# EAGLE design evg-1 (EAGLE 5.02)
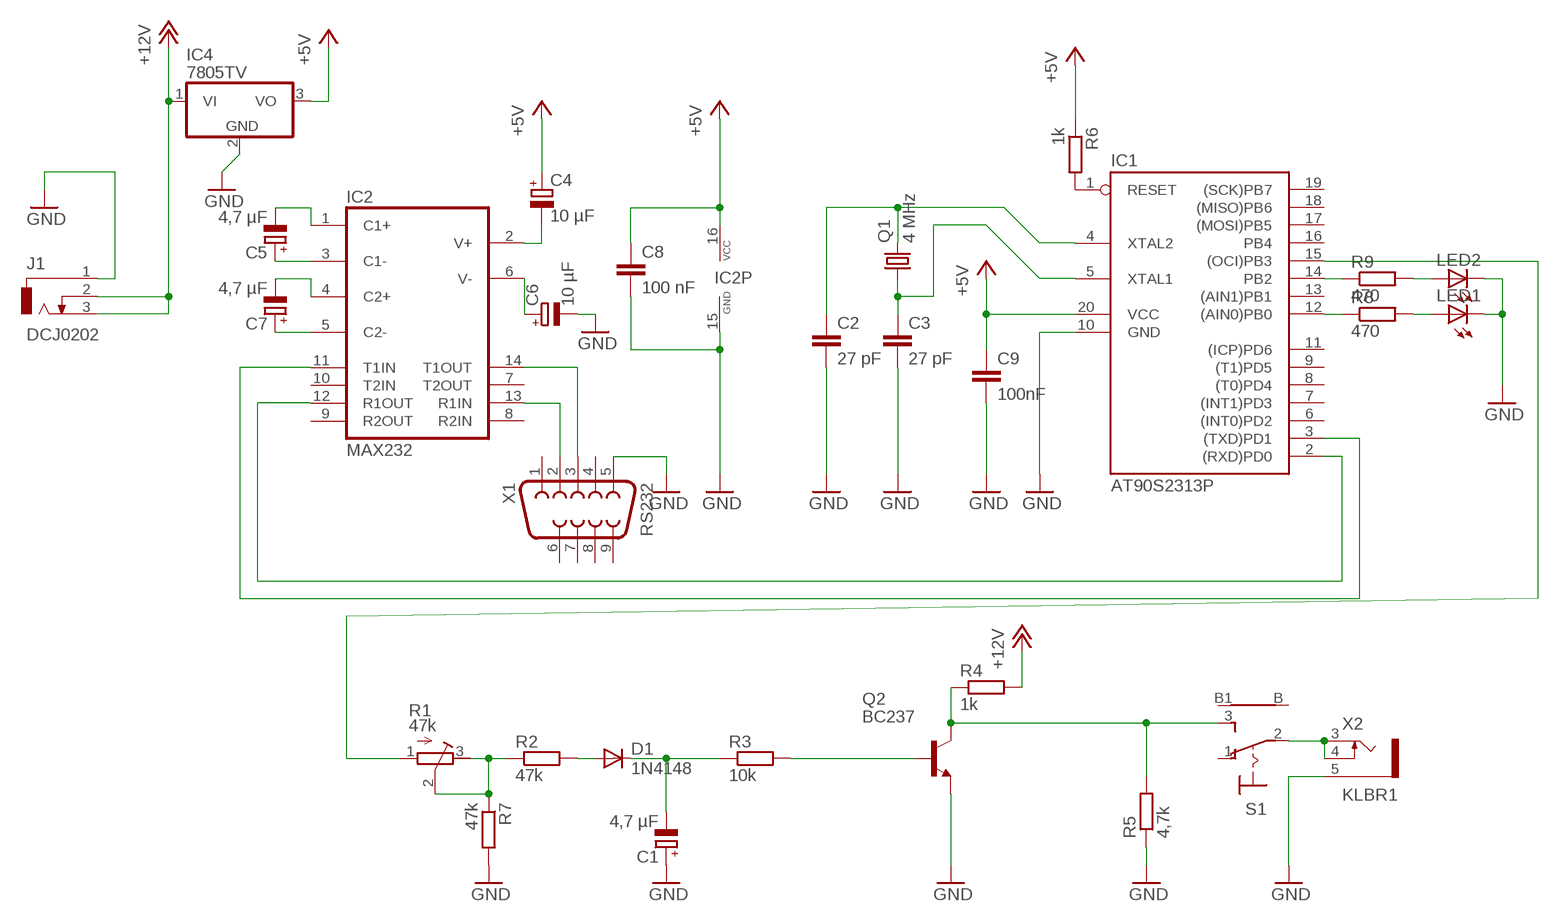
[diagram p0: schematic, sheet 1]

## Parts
C1  4,7 µF  CPOL-EUE2.5-6  [E2,5-6]
C2  27 pF  C-EU075-032X103  [C075-032X103]
C3  27 pF  C-EU075-032X103  [C075-032X103]
C4  10 µF  CPOL-EUE2.5-6  [E2,5-6]
C5  4,7 µF  CPOL-EUE2.5-6  [E2,5-6]
C6  10 µF  CPOL-EUE2.5-6  [E2,5-6]
C7  4,7 µF  CPOL-EUE2.5-6  [E2,5-6]
C8  100 nF  C-EU075-032X103  [C075-032X103]
C9  100nF  C-EU075-032X103  [C075-032X103]
D1  1N4148  [DO35-10]
IC1  AT90S2313P  [DIL20]
IC2  MAX232  [DIL16]
IC4  7805TV  [TO220V]
J1  DCJ0202  [DCJ0202]
LED1  LED3MM  [LED3MM]
LED2  LED3MM  [LED3MM]
Q1  4 MHz  CRYSTALHC18U-V  [HC18U-V]
Q2  BC237  [TO92]
R1  47k  R-TRIMM74W  [RTRIM74W]
R2  47k  R-EU_0207/15  [0207/15]
R3  10k  R-EU_0204/7  [0204/7]
R4  1k  R-EU_0207/15  [0207/15]
R5  4,7k  R-EU_0204/7  [0204/7]
R6  1k  R-EU_0204/7  [0204/7]
R7  47k  R-EU_0204/7  [0204/7]
R8  470  R-EU_0204/2V  [0204V]
R9  470  R-EU_0204/2V  [0204V]
S1  9070-1W  [9070-1W]
X1  RS232  F09H  [F09H]
X2  KLBR1  [KLBR1]

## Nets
+5V: C4.+ C8.1 C9.1 IC1.20(VCC) IC2.16(VCC) IC4.3(VO) R6.1
+12V: IC4.1(VI) J1.2 J1.3 R4.2
C6: C6.+ IC2.6(V-)
GND: C1.+ C2.2 C3.2 C6.- C8.2 C9.2 IC1.10(GND) IC2.15(GND) IC4.2(GND) J1.1 LED1.K(C) LED2.K(C) Q2.1(E) R5.1 R7.2 X1.5 X2.5
N$1: IC1.2((RXD)PD0) IC2.12(R1OUT)
N$2: IC1.1(RESET) R6.2
N$3: IC1.3((TXD)PD1) IC2.11(T1IN)
N$4: C7.+ IC2.5(C2-)
N$5: C5.+ IC2.3(C1-)
N$6: C2.1 IC1.4(XTAL2) Q1.2
N$7: C7.- IC2.4(C2+)
N$8: C5.- IC2.1(C1+)
N$9: C4.- IC2.2(V+)
N$10: S1.2(P) X2.3 X2.4
N$11: C3.1 IC1.5(XTAL1) Q1.1
N$13: IC2.13(R1IN) X1.2
N$14: IC2.14(T1OUT) X1.3
N$15: Q2.3(C) R4.1 R5.2 S1.3(S)
N$16: D1.A R2.2
N$17: R1.2(S) R1.3(A) R2.1 R7.1
N$18: C1.- D1.C R3.1
N$19: Q2.2(B) R3.2
N$20: IC1.14(PB2) R9.1
N$21: IC1.12((AIN0)PB0) R8.1
N$22: LED2.A R9.2
N$23: IC1.15((OCI)PB3) R1.1(E)
N$24: LED1.A R8.2
Unconnected: IC1.6((INT0)PD2) IC1.7((INT1)PD3) IC1.8((T0)PD4) IC1.9((T1)PD5) IC1.11((ICP)PD6) IC1.13((AIN1)PB1) IC1.16(PB4) IC1.17((MOSI)PB5) IC1.18((MISO)PB6) IC1.19((SCK)PB7) IC2.7(T2OUT) IC2.8(R2IN) IC2.9(R2OUT) IC2.10(T2IN) S1.1(O) S1.B S1.B1 X1.1 X1.4 X1.6 X1.7 X1.8 X1.9

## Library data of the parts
C1 C4-C7 = resistor:CPOL-EU: POLARIZED CAPACITOR, European symbol
C2 C3 C8 C9 = resistor:C-EU: CAPACITOR, European symbol
D1 = diode:1N4148: DIODE
IC1 = atmel:AT90S2313: MICROCONTROLLER 2 Kbytes FLASH 128 bytes SRAM 128 bytes EEPROM UART
IC2 = maxim:MAX232: RS232 TRANSEIVER
IC4 = linear:78*: Positive VOLTAGE REGULATOR Source: http://cache.national.com/ds/LM/LM78L05.pdf http://www.fairchildsemi.com/ds/LM/LM7805.pdf
J1 = con-jack:DCJ0202: DC POWER JACK Source: DCJ0202.pdf
LED1 LED2 = led:LED: LED
Q1 = crystal:CRYSTAL: CRYSTAL
Q2 = transistor-npn:BC237: NPN Transistor
R1 = resistor:R-TRIMM: Trimm resistor
R2-R9 = resistor:R-EU_: RESISTOR, European symbol
S1 = switch:9070-1W: TOGGLE SWITCH Marquardt
X1 = con-subd:F09: SUB-D
X2 = con-lumberg:KLBR?: Jack connectors according to JISC 6560, 2.5mm / 3.5 mm Klinkensteckverbinder nach JISC 6560, 2.5mm / 3,5 mm Source: http://www.lumberg.com/Produkte/PDFs/KLBR2.pdf www.lumberg.com/Produkte/PDFs/KLBR1.pdf

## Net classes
0 default: width 0.406 mm
1 supply: width 1.143 mm

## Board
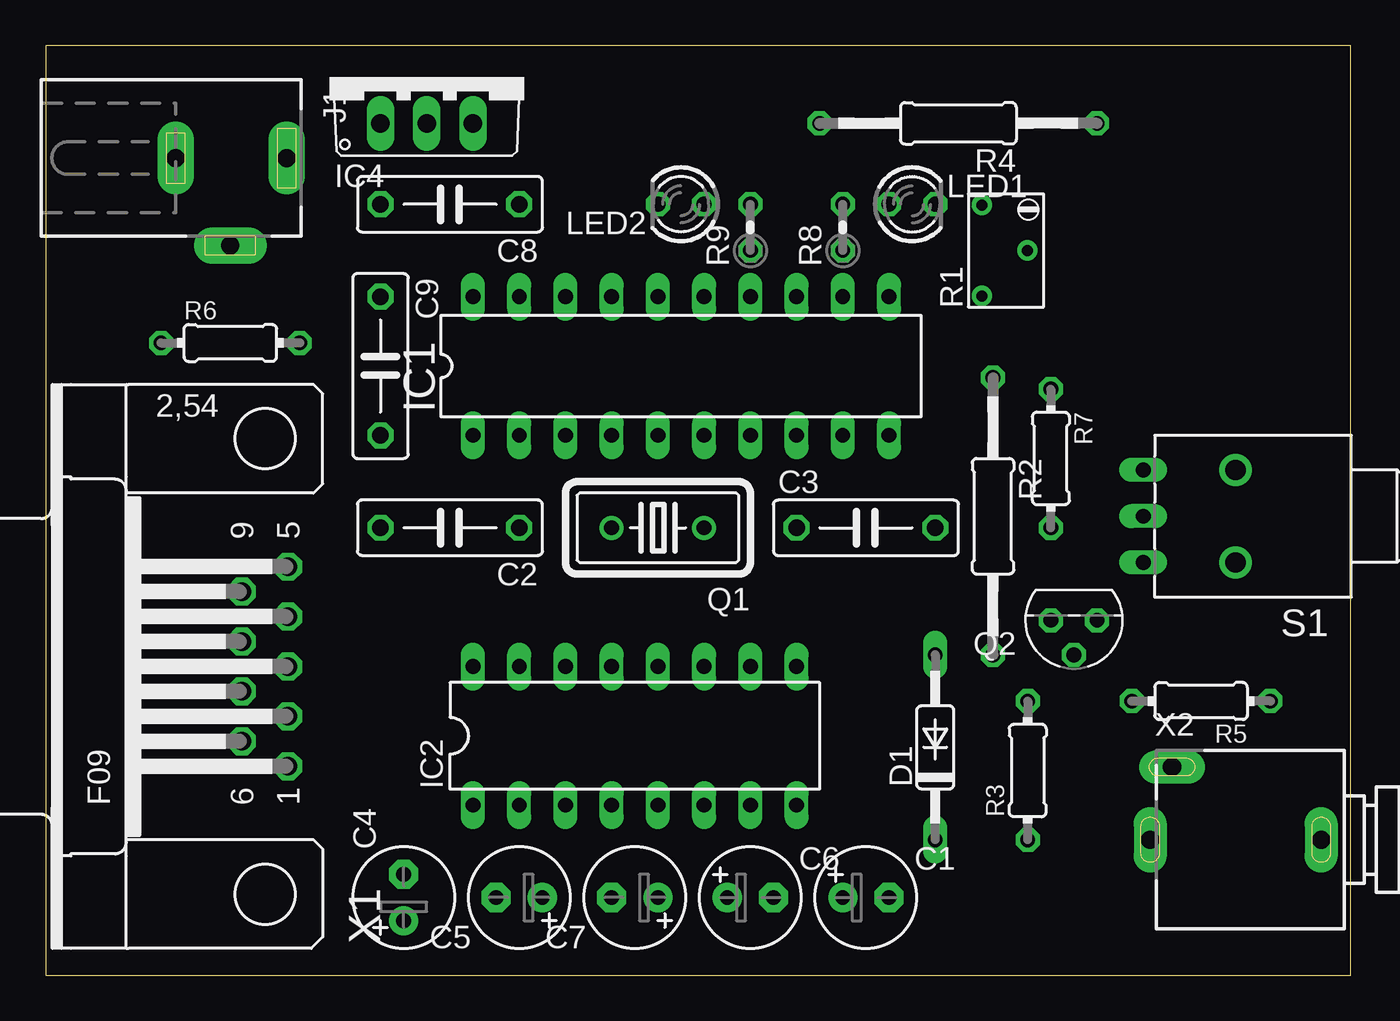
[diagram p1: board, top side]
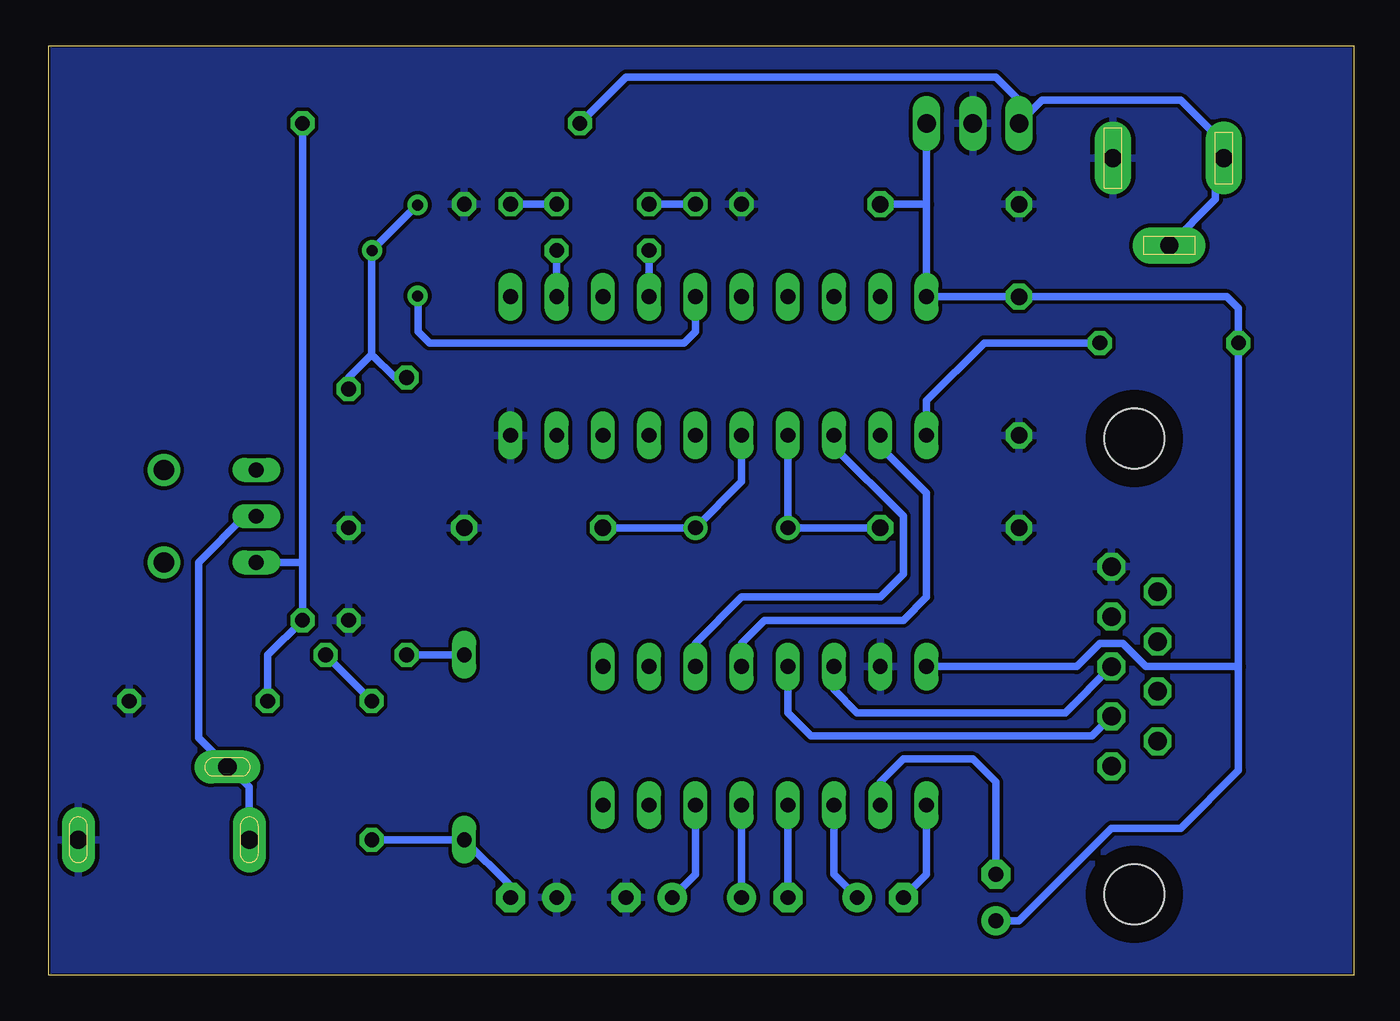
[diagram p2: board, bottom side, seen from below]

Size 71.73 x 51.1 mm. Coordinates in mm from the lower left corner, seen from the top.
Outline: 0,0 71.73,0 71.73,51.1 0,51.1 0,0
Copper layers (1*16): Top 0.035mm / dielectric 1.5mm / Bottom 0.035mm
Design rules "default *": minimum track width 10mil, minimum drill 24mil, track to track 8mil, track to pad 8mil, pad to pad 8mil, via to via 8mil, smd to smd 8mil, copper to edge 4mil, drill to drill 8mil, minimum pad ring 10mil, minimum via ring 8mil, stop-mask expansion 4mil, vias tented up to drill 0mil, thermal gap 10mil

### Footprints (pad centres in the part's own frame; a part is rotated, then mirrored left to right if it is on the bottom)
E2,5-6 = drill 0.813 pad 1.6 round: + -1.27,0 | drill 0.813 pad 1.6 octagon: - 1.27,0
C075-032X103 = drill 0.914 octagon: 1 -3.81,0; 2 3.81,0
DO35-10 = drill 0.813 long: A 5.08,0; C -5.08,0
DIL20 = drill 0.813 long: 1 -11.43,-3.81; 2 -8.89,-3.81; 3 -6.35,-3.81; 4 -3.81,-3.81; 5 -1.27,-3.81; 6 1.27,-3.81; 7 3.81,-3.81; 8 6.35,-3.81; 9 8.89,-3.81; 10 11.43,-3.81; 11 11.43,3.81; 12 8.89,3.81; 13 6.35,3.81; 14 3.81,3.81; 15 1.27,3.81; 16 -1.27,3.81; 17 -3.81,3.81; 18 -6.35,3.81; 19 -8.89,3.81; 20 -11.43,3.81
DIL16 = drill 0.813 long: 1 -8.89,-3.81; 2 -6.35,-3.81; 3 -3.81,-3.81; 4 -1.27,-3.81; 5 1.27,-3.81; 6 3.81,-3.81; 7 6.35,-3.81; 8 8.89,-3.81; 9 8.89,3.81; 10 6.35,3.81; 11 3.81,3.81; 12 1.27,3.81; 13 -1.27,3.81; 14 -3.81,3.81; 15 -6.35,3.81; 16 -8.89,3.81
TO220V = drill 1.016 long: 1 -2.54,-2.54; 2 0,-2.54; 3 2.54,-2.54
DCJ0202 = drill 1 pad 2 long: 1 0,3.1; 2 4.8,0; 3 0,-3
LED3MM = drill 0.813 octagon: A -1.27,0; K 1.27,0
HC18U-V = drill 0.813 round: 1 -2.54,0; 2 2.54,0
TO92 = drill 0.813 octagon: 1 1.27,0; 2 0,1.905; 3 -1.27,0
RTRIM74W = drill 0.61 round: 1 -1.25,-2.5; 2 1.25,0; 3 -1.25,2.5
0207/15 = drill 0.813 octagon: 1 -7.62,0; 2 7.62,0
0204/7 = drill 0.813 octagon: 1 -3.81,0; 2 3.81,0
0204V = drill 0.813 octagon: 1 -1.27,0; 2 1.27,0
9070-1W = drill 0.813 long: 1 5.08,-2.54; 2 5.08,0; 3 5.08,2.54 | drill 1.118 pad 1.778 round: B 0,-2.54; B1 0,2.54
F09H = drill 1.016 octagon: 1 -5.486,-1.27; 2 -2.743,-1.27; 3 0,-1.27; 4 2.743,-1.27; 5 5.486,-1.27; 6 -4.115,1.27; 7 -1.372,1.27; 8 1.372,1.27; 9 4.115,1.27 | hole 3.302: -12.522,0; 12.522,0
KLBR1 = drill 1 pad 1.8 long: 3 0,-4.7; 4 -4,-3.5; 5 0,4.7

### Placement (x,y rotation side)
C1  45.08,4.28 0 top
C2  22.22,24.6 180 top
C3  45.08,24.6 0 top
C4  19.68,4.28 90 top
C5  26.03,4.28 180 top
C6  38.73,4.28 0 top
C7  32.38,4.28 180 top
C8  22.22,42.38 180 top
C9  18.41,33.49 270 top
D1  48.89,12.54 90 top
IC1  34.92,33.49 0 top
IC2  32.38,13.17 0 top
IC4  20.95,49.37 0 top
J1  10.16,44.92 270 top
LED1  47.62,42.38 0 top
LED2  34.92,42.38 180 top
Q1  33.65,24.6 180 top
Q2  56.51,19.52 180 top
R1  52.7,39.84 0 top
R2  52.07,25.23 270 top
R3  53.97,11.27 90 top
R4  50.16,46.82 180 top
R5  63.5,15.08 180 top
R6  10.16,34.76 0 top
R7  55.24,28.41 270 top
R8  43.81,41.11 90 top
R9  38.73,41.11 90 top
S1  65.4,25.23 180 top
X1  12.06,16.98 90 top
X2  65.4,7.46 270 top

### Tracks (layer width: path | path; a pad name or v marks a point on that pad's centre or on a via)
+5V
  Bottom 0.406: 23.49,42.38 IC1.20 C9.1 6.98,37.3 6.34,36.66 R6.1 6.34,16.98 | 23.49,42.38 IC4.3 | 23.49,42.38 C8.1 | C4.+ 18.41,3.01 13.33,8.09 9.52,8.09 6.34,11.27 6.34,16.98 | IC2.16 15.24,16.98 13.97,18.25 12.7,18.25 11.43,16.98 6.34,16.98
+12V
  Bottom 0.406: 7.62,44.92 7.62,46.19 9.52,48.09 17.14,48.09 IC4.1 18.41,48.09 19.68,49.37 40,49.37 R4.2 | 7.62,44.92 J1.3 | J1.2 7.62,42.66 7.62,44.92
C6
  Bottom 0.406: IC2.6 36.19,5.55 C6.+
GND
  pour Bottom: -1.27,51.91 -1.27,-1.44 73.66,-1.44 73.66,51.91
N$1
  Bottom 0.406: IC1.2 26.03,29.04 23.49,26.5 23.49,20.79 24.76,19.52 32.38,19.52 33.65,18.25 IC2.12
N$2
  Bottom 0.406: R6.2 20.31,34.76 23.49,31.58 IC1.1
N$3
  Bottom 0.406: IC1.3 28.57,29.04 24.76,25.23 24.76,22.06 26.03,20.79 33.65,20.79 36.19,18.25 IC2.11
N$4
  Bottom 0.406: C7.+ IC2.5
N$5
  Bottom 0.406: IC2.3 28.57,5.55 C5.+
N$6
  Bottom 0.406: C2.1 Q1.2 IC1.4
N$7
  Bottom 0.406: C7.- IC2.4
N$8
  Bottom 0.406: IC2.1 23.49,5.55 C5.-
N$9
  Bottom 0.406: C4.- 19.68,10.63 20.95,11.9 24.76,11.9 26.03,10.63 IC2.2
N$10
  Bottom 0.406: X2.3 60.7,10.38 61.78,11.46 X2.4 63.5,13.05 63.5,22.7 60.96,25.23 S1.2
N$11
  Bottom 0.406: IC1.5 33.65,27.14 Q1.1 C3.1
N$13
  Bottom 0.406: X1.2 14.4,13.17 29.84,13.17 31.11,14.44 IC2.13
N$14
  Bottom 0.406: X1.3 15.87,14.44 27.3,14.44 28.57,15.71 IC2.14
N$15
  Bottom 0.406: 57.78,22.7 R4.1 | R5.2 59.69,17.61 Q2.3 57.78,22.7 | 57.78,22.7 S1.3
N$16
  Bottom 0.406: D1.A R2.2
N$17
  Bottom 0.406: R1.3 51.47,42.34 53.97,39.84 | R2.1 52.7,32.85 53.97,34.12 | 53.97,39.84 R1.2 | 53.97,34.12 53.97,39.84 | R7.1 55.24,32.85 53.97,34.12
N$18
  Bottom 0.406: R3.1 D1.C 46.35,4.92 C1.-
N$19
  Bottom 0.406: R3.2 Q2.2
N$20
  Bottom 0.406: IC1.14 R9.1
N$21
  Bottom 0.406: IC1.12 R8.1
N$22
  Bottom 0.406: LED2.A R9.2
N$23
  Bottom 0.406: IC1.15 36.19,35.39 36.83,34.76 50.8,34.76 51.43,35.39 51.43,37.3 51.45,37.32 R1.1
N$24
  Bottom 0.406: R8.2 LED1.A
